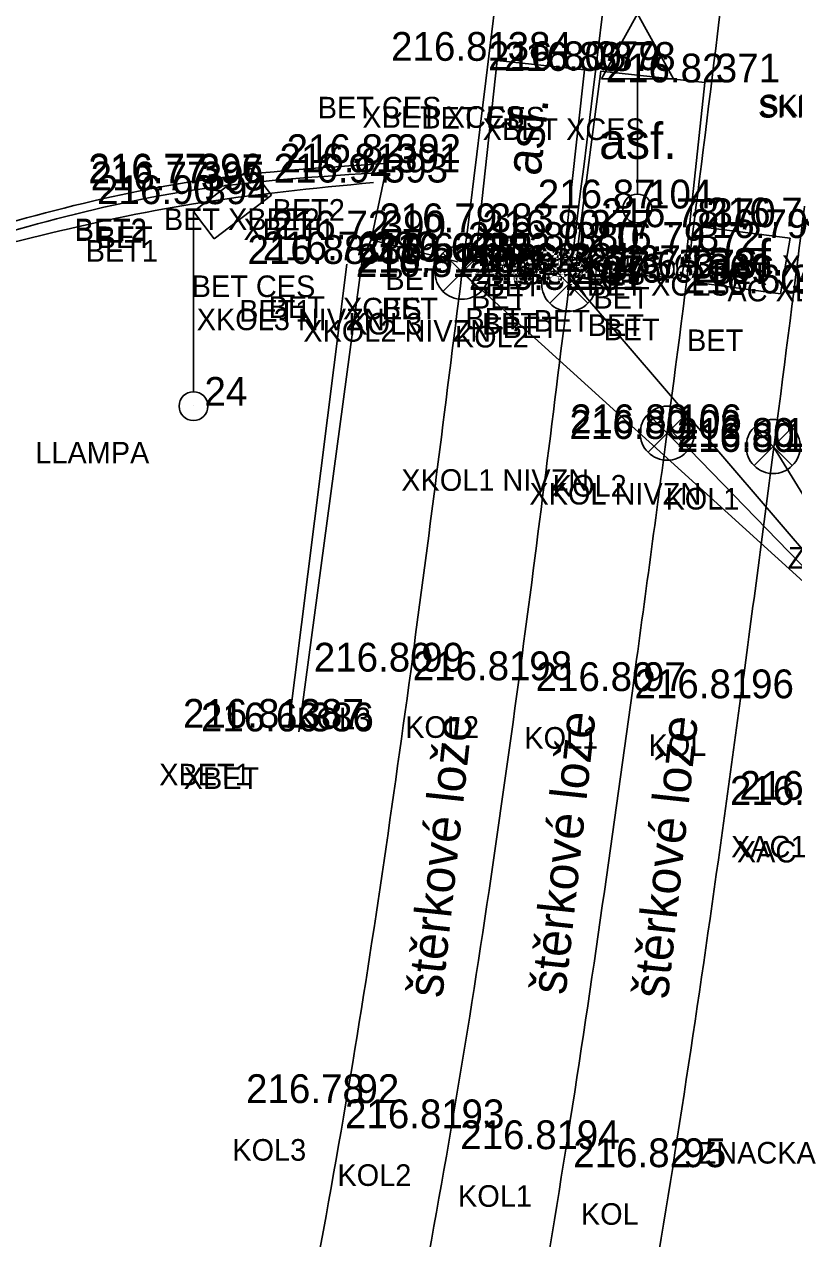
# Model space of a CAD drawing. Extents: x -471047 to -470889, y -1102859 to -1102000.
# Drawn here: x -471009.19 to -470998.51, y -1102775.7 to -1102758.84 of the extents above; entities that cross this region are included whole.
import ezdxf

# ---------------------------------------------------------------- set-up
doc = ezdxf.new("R2010")
doc.units = 0
for name, color, linetype in [('Vrstva 1', 7, 'Continuous'), ('Vrstva 19', 7, 'Continuous'), ('Vrstva 22', 7, 'Continuous'), ('Vrstva 23', 7, 'Continuous'), ('Vrstva 34', 7, 'Continuous'), ('Vrstva 35', 7, 'Continuous'), ('Vrstva 36', 7, 'Continuous'), ('Vrstva 37', 7, 'Continuous'), ('Vrstva 38', 7, 'Continuous'), ('Vrstva 5', 7, 'Continuous'), ('Vrstva 7', 7, 'Continuous'), ('Vrstva 8', 7, 'Continuous')]:
    doc.layers.add(name, color=color, linetype=linetype)

msp = doc.modelspace()

# ---------------------------------------------------------------- linework, layer by layer
at = {"layer": 'Vrstva 1'}
for points in [[(-471040.344, -1102858.385), (-471031.676, -1102846.187), (-471026.357, -1102838.629), (-471023.212, -1102833.975), (-471019.21, -1102827.465), (-471016.861, -1102823.272), (-471013.099, -1102815.912), (-471010.824, -1102810.955), (-471007.329, -1102802.292), (-471005.34, -1102796.515), (-471002.842, -1102787.838), (-471001.3, -1102780.997), (-471000.19, -1102774.713), (-470999.247, -1102768.204), (-470998.794, -1102764.784), (-470997.199, -1102751.812), (-470994.899, -1102732.807), (-470992.551, -1102713.262), (-470990.326, -1102694.887), (-470988.122, -1102676.57), (-470985.812, -1102657.305), (-470983.537, -1102638.407), (-470981.386, -1102620.622), (-470979.843, -1102608.014), (-470976.377, -1102579.253), (-470972.945, -1102550.69), (-470970.475, -1102530.206), (-470967.905, -1102508.801), (-470965.053, -1102485.131), (-470962.734, -1102465.9), (-470960.173, -1102444.812), (-470957.795, -1102425.103), (-470954.965, -1102401.839), (-470953.834, -1102392.574), (-470952.33, -1102379.985), (-470950.744, -1102366.853), (-470948.978, -1102352.106), (-470947.037, -1102335.844), (-470944.949, -1102318.462), (-470944.013, -1102310.745), (-470942.39, -1102297.267), (-470939.519, -1102273.45), (-470937.593, -1102257.43), (-470936.064, -1102244.81), (-470934.114, -1102228.634), (-470931.621, -1102207.856), (-470929.536, -1102190.857), (-470926.572, -1102166.31), (-470924.91, -1102152.663), (-470923.413, -1102140.333), (-470921.923, -1102127.669), (-470921.155, -1102120.084), (-470920.446, -1102109.574), (-470919.912, -1102099.137), (-470919.63, -1102088.981), (-470919.523, -1102081.193), (-470919.563, -1102070.395), (-470919.714, -1102064.236), (-470920.134, -1102054.704), (-470920.462, -1102047.615), (-470920.599, -1102044.52), (-470920.743, -1102041.873), (-470921.125, -1102034.455), (-470921.774, -1102030.337), (-470922.418, -1102027.787), (-470923.734, -1102023.93), (-470924.872, -1102021.434), (-470926.752, -1102018.182), (-470927.953, -1102016.45), (-470929.616, -1102014.424), (-470932.252, -1102011.756), (-470935.111, -1102009.425), (-470938.391, -1102007.371), (-470942.651, -1102005.401)], [(-471041.328, -1102857.18), (-471032.144, -1102844.242), (-471027.583, -1102837.763), (-471024.388, -1102833.028), (-471020.451, -1102826.6), (-471018.089, -1102822.378), (-471014.542, -1102815.445), (-471012.233, -1102810.418), (-471009.247, -1102803.108), (-471006.795, -1102796.098), (-471004.315, -1102787.532), (-471002.782, -1102780.723), (-471001.674, -1102774.458), (-471000.75, -1102768.095), (-471000.28, -1102764.601), (-470998.692, -1102751.741), (-470996.378, -1102732.635), (-470994.028, -1102713.058), (-470991.808, -1102694.749), (-470989.616, -1102676.447), (-470987.284, -1102657.013), (-470985.031, -1102638.272), (-470982.87, -1102620.431), (-470981.334, -1102607.933), (-470977.881, -1102579.263), (-470974.429, -1102550.492), (-470971.964, -1102530.054), (-470969.391, -1102508.607), (-470966.54, -1102484.984), (-470964.231, -1102465.853), (-470961.679, -1102444.752), (-470959.304, -1102425.078), (-470956.455, -1102401.634), (-470955.339, -1102392.489), (-470953.812, -1102379.71), (-470952.249, -1102366.808), (-470950.479, -1102352.023), (-470948.536, -1102335.868), (-470946.426, -1102318.233), (-470945.493, -1102310.531), (-470943.864, -1102297.013), (-470940.984, -1102273.071), (-470939.078, -1102257.195), (-470937.559, -1102244.684), (-470935.592, -1102228.353), (-470933.101, -1102207.653), (-470931.011, -1102190.57), (-470928.046, -1102166.021), (-470926.409, -1102152.578), (-470924.898, -1102140.121), (-470923.427, -1102127.544), (-470922.647, -1102119.826), (-470921.919, -1102109.229), (-470921.42, -1102099.134), (-470921.127, -1102089.016), (-470921.023, -1102081.453), (-470921.061, -1102070.468), (-470921.209, -1102064.314), (-470921.666, -1102053.966), (-470922.156, -1102043.345), (-470922.299, -1102039.934), (-470922.637, -1102034.36), (-470923.091, -1102031.241), (-470923.847, -1102028.247), (-470925.083, -1102024.594), (-470926.222, -1102022.086), (-470928.04, -1102018.943), (-470929.138, -1102017.357), (-470930.929, -1102015.175), (-470933.062, -1102013.049), (-470936.379, -1102010.368), (-470939.169, -1102008.662), (-470942.899, -1102006.906), (-470945.661, -1102005.908)], [(-471043.557, -1102855.955), (-471035.129, -1102844.026), (-471029.872, -1102836.499), (-471026.577, -1102831.578), (-471022.675, -1102825.415), (-471020.123, -1102821.053), (-471016.667, -1102814.59), (-471014.208, -1102809.45), (-471011.177, -1102802.451), (-471008.55, -1102795.333), (-471006.082, -1102787.209), (-471004.464, -1102780.376), (-471003.265, -1102774.167), (-471002.327, -1102767.948), (-471001.636, -1102762.527), (-471000.297, -1102751.605), (-470997.959, -1102732.524), (-470995.602, -1102712.802), (-470993.412, -1102694.623), (-470991.21, -1102676.17), (-470988.891, -1102656.857), (-470986.625, -1102638.083), (-470984.455, -1102620.195), (-470982.936, -1102607.733), (-470979.497, -1102579.223), (-470976.023, -1102550.279), (-470973.554, -1102529.822), (-470970.991, -1102508.497), (-470968.146, -1102484.787), (-470965.835, -1102465.72), (-470963.284, -1102444.529), (-470960.91, -1102424.942), (-470958.043, -1102401.343), (-470956.946, -1102392.356), (-470955.396, -1102379.408), (-470953.851, -1102366.636), (-470952.049, -1102351.733), (-470950.124, -1102335.611), (-470948.034, -1102318.083), (-470947.094, -1102310.328), (-470945.421, -1102296.51), (-470942.58, -1102272.848), (-470940.675, -1102256.948), (-470939.176, -1102244.526), (-470937.187, -1102228.174), (-470934.708, -1102207.467), (-470932.621, -1102190.433), (-470929.634, -1102165.778), (-470928.004, -1102152.415), (-470926.45, -1102139.595), (-470925.003, -1102127.418), (-470924.249, -1102119.695), (-470923.515, -1102109.093), (-470923.018, -1102099.069), (-470922.711, -1102088.911), (-470922.643, -1102081.356), (-470922.797, -1102070.414), (-470923.018, -1102064.454), (-470923.52, -1102053.203), (-470923.823, -1102047.529), (-470924.123, -1102041.506), (-470924.462, -1102037.486), (-470924.934, -1102031.904), (-470925.664, -1102028.672), (-470926.771, -1102025.506), (-470927.959, -1102022.914), (-470929.674, -1102020.028), (-470930.76, -1102018.498), (-470932.447, -1102016.478), (-470935.215, -1102013.816), (-470937.644, -1102011.98), (-470940.381, -1102010.371), (-470943.968, -1102008.669), (-470947.145, -1102007.524), (-470950.874, -1102006.74)], [(-471044.756, -1102855.056), (-471036.376, -1102843.177), (-471031.167, -1102835.741), (-471027.859, -1102830.8), (-471023.934, -1102824.593), (-471021.43, -1102820.312), (-471018.011, -1102813.91), (-471015.536, -1102808.75), (-471012.578, -1102801.897), (-471009.95, -1102794.77), (-471007.561, -1102786.914), (-471005.936, -1102780.074), (-471004.727, -1102773.818), (-471003.828, -1102767.827), (-471003.121, -1102762.345), (-471001.787, -1102751.467), (-470999.446, -1102732.348), (-470997.073, -1102712.539), (-470994.902, -1102694.521), (-470992.696, -1102676.023), (-470990.376, -1102656.68), (-470988.131, -1102638.071), (-470985.947, -1102620.018), (-470984.417, -1102607.512), (-470980.993, -1102579.08), (-470977.514, -1102550.137), (-470975.048, -1102529.649), (-470972.488, -1102508.37), (-470969.618, -1102484.508), (-470967.34, -1102465.669), (-470964.767, -1102444.39), (-470962.402, -1102424.781), (-470959.534, -1102401.193), (-470958.432, -1102392.151), (-470956.883, -1102379.208), (-470955.335, -1102366.424), (-470953.535, -1102351.506), (-470951.606, -1102335.399), (-470949.519, -1102317.94), (-470948.575, -1102310.159), (-470946.889, -1102296.144), (-470944.056, -1102272.618), (-470942.139, -1102256.659), (-470940.657, -1102244.341), (-470938.638, -1102227.749), (-470936.19, -1102207.298), (-470934.102, -1102190.255), (-470931.124, -1102165.639), (-470929.492, -1102152.254), (-470927.915, -1102139.252), (-470926.46, -1102127.103), (-470925.74, -1102119.604), (-470925.012, -1102108.913), (-470924.523, -1102099.054), (-470924.217, -1102088.866), (-470924.148, -1102081.334), (-470924.301, -1102070.391), (-470924.518, -1102064.43), (-470924.97, -1102054.435), (-470925.588, -1102041.569), (-470925.963, -1102035.313), (-470926.405, -1102032.225), (-470927.078, -1102029.198), (-470928.123, -1102026.148), (-470929.318, -1102023.558), (-470930.84, -1102020.97), (-470931.868, -1102019.515), (-470933.443, -1102017.605), (-470936.26, -1102014.885), (-470938.429, -1102013.255), (-470941.213, -1102011.639), (-470944.847, -1102009.927), (-470947.723, -1102008.912), (-470951.444, -1102008.161), (-470954.511, -1102007.931), (-470957.895, -1102008.041)]]:
    msp.add_spline(points, degree=3, dxfattribs=at)
at = {"layer": 'Vrstva 19'}
for p, q in [((-471000.68, -1102758.7), (-471001.18, -1102759.6)), ((-471000.68, -1102758.7), (-471000.18, -1102759.6)), ((-471000.18, -1102759.6), (-471001.18, -1102759.6)), ((-471000.68, -1102759.6), (-471000.68, -1102761.2))]:
    msp.add_line(p, q, dxfattribs=at)
msp.add_circle((-471000.68, -1102761.4), 0.2, dxfattribs=at)
at = {"layer": 'Vrstva 22'}
for q in [(-471003.11, -1102762.29), (-471001.617, -1102762.368), (-471000.259, -1102764.436), (-470998.79, -1102764.71)]:
    msp.add_line((-470996.706, -1102768.099), q, dxfattribs=at)
at = {"layer": 'Vrstva 23'}
for p, q in [((-471006.049, -1102760.839), (-471006.844, -1102761.444)), ((-471005.759, -1102761.216), (-471006.049, -1102760.839)), ((-471006.556, -1102761.822), (-471005.759, -1102761.216)), ((-471006.844, -1102761.444), (-471006.844, -1102763.944)), ((-471006.844, -1102761.444), (-471006.556, -1102761.822))]:
    msp.add_line(p, q, dxfattribs=at)
msp.add_circle((-471006.844, -1102764.144), 0.2, dxfattribs=at)
at = {"layer": 'Vrstva 34'}
for p, q in [((-471002.63, -1102759.35), (-471002.63, -1102759.35)), ((-471001.41, -1102759.48), (-471001.41, -1102759.48)), ((-471001.19, -1102759.49), (-471001.19, -1102759.49)), ((-470999.74, -1102759.65), (-470999.74, -1102759.65)), ((-471004.17, -1102760.77), (-471004.17, -1102760.77)), ((-471004.18, -1102760.9), (-471004.18, -1102760.9)), ((-471006.92, -1102761.04), (-471006.92, -1102761.04)), ((-471006.92, -1102761.05), (-471006.92, -1102761.05)), ((-471006.89, -1102761.15), (-471006.89, -1102761.15)), ((-471004.35, -1102761.04), (-471004.35, -1102761.04)), ((-471006.84, -1102761.34), (-471006.84, -1102761.34)), ((-471000.68, -1102761.4), (-471000.68, -1102761.4)), ((-470999.8, -1102761.66), (-470999.8, -1102761.66)), ((-471004.38, -1102761.83), (-471004.38, -1102761.83)), ((-471002.88, -1102761.73), (-471002.88, -1102761.73)), ((-471001.49, -1102761.82), (-471001.49, -1102761.82)), ((-470998.56, -1102761.81), (-470998.56, -1102761.81)), ((-471001.69, -1102761.99), (-471001.69, -1102761.99)), ((-470999.99, -1102761.99), (-470999.99, -1102761.99)), ((-471004.71, -1102762.17), (-471004.71, -1102762.17)), ((-471004.5, -1102762.12), (-471004.5, -1102762.12)), ((-471003.18, -1102762.14), (-471003.18, -1102762.14)), ((-471002.93, -1102762.14), (-471002.93, -1102762.14)), ((-471003.12, -1102762.35), (-471003.12, -1102762.35)), ((-471003.11, -1102762.29), (-471003.11, -1102762.29)), ((-471001.77, -1102762.28), (-471001.77, -1102762.28)), ((-471001.54, -1102762.35), (-471001.54, -1102762.35)), ((-471000.82, -1102762.31), (-471000.82, -1102762.31)), ((-471001.63, -1102762.45), (-471001.63, -1102762.45)), ((-471001.25, -1102762.4), (-471001.25, -1102762.4)), ((-471000.07, -1102762.37), (-471000.07, -1102762.37)), ((-470999.85, -1102762.43), (-470999.85, -1102762.43)), ((-471001.64, -1102762.53), (-471001.64, -1102762.53)), ((-470998.69, -1102762.58), (-470998.69, -1102762.58)), ((-471006.84, -1102764.14), (-471006.84, -1102764.14)), ((-471000.27, -1102764.52), (-471000.27, -1102764.52)), ((-471000.28, -1102764.6), (-471000.28, -1102764.6)), ((-470998.79, -1102764.71), (-470998.79, -1102764.71)), ((-470998.79, -1102764.78), (-470998.79, -1102764.78)), ((-471003.83, -1102767.83), (-471003.83, -1102767.83)), ((-471002.33, -1102767.95), (-471002.33, -1102767.95)), ((-471000.75, -1102768.1), (-471000.75, -1102768.1)), ((-470999.25, -1102768.2), (-470999.25, -1102768.2)), ((-471005.52, -1102768.61), (-471005.52, -1102768.61)), ((-471005.38, -1102768.66), (-471005.38, -1102768.66)), ((-471004.73, -1102773.82), (-471004.73, -1102773.82)), ((-471003.27, -1102774.17), (-471003.27, -1102774.17)), ((-471001.67, -1102774.46), (-471001.67, -1102774.46)), ((-471000.19, -1102774.71), (-471000.19, -1102774.71))]:
    msp.add_line(p, q, dxfattribs=at)
at = {"layer": 'Vrstva 37'}
for p, q in [((-471003.38, -1102762.021), (-471003.115, -1102762.286)), ((-471002.85, -1102762.021), (-471003.115, -1102762.286)), ((-471002.85, -1102762.021), (-471002.85, -1102762.021)), ((-471001.897, -1102762.186), (-471001.632, -1102762.451)), ((-471001.367, -1102762.186), (-471001.632, -1102762.451)), ((-471001.367, -1102762.186), (-471001.367, -1102762.186)), ((-471003.115, -1102762.286), (-471003.38, -1102762.551)), ((-471003.115, -1102762.286), (-471002.85, -1102762.551)), ((-471001.632, -1102762.451), (-471001.897, -1102762.716)), ((-471001.632, -1102762.451), (-471001.367, -1102762.716)), ((-471000.531, -1102764.255), (-471000.266, -1102764.52)), ((-471000.001, -1102764.255), (-471000.266, -1102764.52)), ((-471000.001, -1102764.255), (-471000.001, -1102764.255)), ((-471000.266, -1102764.52), (-471000.531, -1102764.785)), ((-471000.266, -1102764.52), (-471000.001, -1102764.785)), ((-470999.059, -1102764.44), (-470998.794, -1102764.705)), ((-470998.529, -1102764.44), (-470998.794, -1102764.705)), ((-470998.529, -1102764.44), (-470998.529, -1102764.44)), ((-470998.794, -1102764.705), (-470999.059, -1102764.97)), ((-470998.794, -1102764.705), (-470998.529, -1102764.97))]:
    msp.add_line(p, q, dxfattribs=at)
for centre, start, end in [((-471003.115, -1102762.286), 135, 224.9643), ((-471003.115, -1102762.286), 45, 134.9643), ((-471003.115, -1102762.286), 315, 44.9643), ((-471001.632, -1102762.451), 135, 224.9643), ((-471001.632, -1102762.451), 45, 134.9643), ((-471001.632, -1102762.451), 315, 44.9643), ((-471003.115, -1102762.286), 225, 314.9643), ((-471001.632, -1102762.451), 225, 314.9643), ((-471000.266, -1102764.52), 45, 134.9643), ((-471000.266, -1102764.52), 135, 224.9643), ((-471000.266, -1102764.52), 315, 44.9643), ((-470998.794, -1102764.705), 45, 134.9643), ((-470998.794, -1102764.705), 135, 224.9643), ((-470998.794, -1102764.705), 315, 44.9643), ((-471000.266, -1102764.52), 225, 314.9643), ((-470998.794, -1102764.705), 225, 314.9643)]:
    msp.add_arc(centre, 0.375, start, end, dxfattribs=at)
at = {"layer": 'Vrstva 5'}
for p, q in [((-471004.177, -1102760.897), (-471004.17, -1102760.774)), ((-471006.92, -1102761.036), (-471006.924, -1102761.047))]:
    msp.add_line(p, q, dxfattribs=at)
msp.add_spline([(-471011.116, -1102762.107), (-471006.92, -1102761.036), (-471004.17, -1102760.774)], degree=3, dxfattribs=at)
at = {"layer": 'Vrstva 7'}
msp.add_line((-471005.523, -1102768.609), (-471004.714, -1102762.172), dxfattribs=at)
msp.add_spline([(-471011.067, -1102762.33), (-471006.844, -1102761.336), (-471004.346, -1102761.039)], degree=3, dxfattribs=at)
at = {"layer": 'Vrstva 8'}
for p, q in [((-471002.884, -1102761.731), (-471002.628, -1102759.346)), ((-471001.413, -1102759.476), (-471002.628, -1102759.346)), ((-471001.413, -1102759.476), (-471001.692, -1102761.986)), ((-471001.492, -1102761.817), (-471001.187, -1102759.492)), ((-470999.743, -1102759.65), (-471001.187, -1102759.492)), ((-470999.743, -1102759.65), (-470999.993, -1102761.987)), ((-471004.379, -1102761.834), (-471004.177, -1102760.897)), ((-470999.853, -1102762.426), (-470999.803, -1102761.655)), ((-470998.557, -1102761.812), (-470999.803, -1102761.655)), ((-471004.5, -1102762.116), (-471004.379, -1102761.834)), ((-471003.177, -1102762.143), (-471004.379, -1102761.834)), ((-471002.934, -1102762.141), (-471002.884, -1102761.731)), ((-471001.54, -1102762.353), (-471001.492, -1102761.817)), ((-470998.557, -1102761.812), (-470998.694, -1102762.584)), ((-471001.692, -1102761.986), (-471001.768, -1102762.282)), ((-470999.993, -1102761.987), (-471000.071, -1102762.373)), ((-471005.38, -1102768.664), (-471004.5, -1102762.116)), ((-471001.768, -1102762.282), (-471002.934, -1102762.141)), ((-471001.251, -1102762.402), (-471001.54, -1102762.353)), ((-471000.824, -1102762.311), (-471001.251, -1102762.402)), ((-471000.071, -1102762.373), (-471000.824, -1102762.311)), ((-470998.694, -1102762.584), (-470999.853, -1102762.426))]:
    msp.add_line(p, q, dxfattribs=at)
msp.add_spline([(-471011.104, -1102762.232), (-471006.89, -1102761.152), (-471004.177, -1102760.897)], degree=3, dxfattribs=at)

# ---------------------------------------------------------------- texts
at = {"layer": 'Vrstva 22'}
for s, p in [('asf.', (-471002.026, -1102760.959)), ('štěrkové lože', (-471001.678, -1102772.327)), ('štěrkové lože', (-471003.389, -1102772.37)), ('štěrkové lože', (-471000.257, -1102772.385))]:
    msp.add_text(s, height=0.5, rotation=83.8735, dxfattribs=at).set_placement(p)
for p in [(-471001.211, -1102760.712), (-470999.718, -1102762.332)]:
    msp.add_text('asf.', height=0.5, dxfattribs=at).set_placement(p)
at = {"layer": 'Vrstva 35'}
for s, p in [('SKRUH', (-470998.985, -1102760.12)), ('BET CES', (-471005.119, -1102760.15)), ('XBET XCES', (-471004.499, -1102760.28)), ('BET CES', (-471003.679, -1102760.29)), ('SKRUH', (-470999.005, -1102760.14)), ('XBET XCES', (-471002.829, -1102760.45)), ('BET2', (-471005.745, -1102761.57)), ('BET XBET2', (-471007.255, -1102761.7)), ('BET2', (-471008.495, -1102761.84)), ('BET2', (-471008.495, -1102761.85)), ('BET', (-471008.19, -1102761.95)), ('XBET1', (-471006.15, -1102761.84)), ('BET1', (-471008.34, -1102762.14)), ('ZNACKA', (-471002.88, -1102762.2)), ('BET CES', (-471002.289, -1102762.46)), ('BET', (-470999.64, -1102762.45)), ('AC XAC2', (-470999.345, -1102762.35)), ('BET CES', (-471006.869, -1102762.63)), ('BET', (-471004.18, -1102762.53)), ('BET', (-471002.79, -1102762.62)), ('XBET XCES', (-471001.649, -1102762.61)), ('BET', (-471002.99, -1102762.79)), ('BET', (-471001.29, -1102762.79)), ('AC XBET', (-470999.43, -1102762.69)), ('BET1', (-471006.21, -1102762.97)), ('BET', (-471005.8, -1102762.92)), ('XCES', (-471004.769, -1102762.94)), ('BET', (-471004.23, -1102762.94)), ('XKOL3 NIVZN', (-471006.799, -1102763.09)), ('KOL3', (-471004.695, -1102763.15)), ('BET', (-471003.07, -1102763.08)), ('BET', (-471002.84, -1102763.15)), ('BET', (-471002.12, -1102763.11)), ('XKOL2 NIVZN', (-471005.319, -1102763.25)), ('KOL2', (-471003.215, -1102763.33)), ('BET', (-471002.55, -1102763.2)), ('BET', (-471001.37, -1102763.17)), ('BET', (-471001.15, -1102763.23)), ('BET', (-470999.99, -1102763.38)), ('LLAMPA', (-471009.04, -1102764.94)), ('XKOL1 NIVZN', (-471003.959, -1102765.32)), ('XKOL NIVZN', (-471002.179, -1102765.51)), ('KOL2', (-471001.855, -1102765.4)), ('KOL1', (-471000.29, -1102765.58)), ('ZNACKA', (-470998.59, -1102766.4)), ('KOL3', (-471005.405, -1102768.63)), ('KOL2', (-471003.905, -1102768.75)), ('KOL1', (-471002.25, -1102768.9)), ('KOL', (-471000.525, -1102769)), ('XBET1', (-471007.32, -1102769.41)), ('XBET', (-471006.98, -1102769.46)), ('XAC1', (-470999.38, -1102770.41)), ('XAC', (-470999.299, -1102770.48)), ('KOL3', (-471006.305, -1102774.62)), ('ZNACKA', (-470999.83, -1102774.66)), ('KOL2', (-471004.845, -1102774.97)), ('KOL1', (-471003.17, -1102775.26)), ('KOL', (-471001.465, -1102775.51))]:
    msp.add_text(s, height=0.3, dxfattribs=at).set_placement(p)
at = {"layer": 'Vrstva 36'}
for s, p in [(' 384', (-471002.63, -1102759.35)), (' 379', (-471001.41, -1102759.48)), (' 378', (-471001.19, -1102759.49)), (' 371', (-470999.74, -1102759.65)), (' 391', (-471004.18, -1102760.9)), (' 392', (-471004.17, -1102760.77)), (' 396', (-471006.92, -1102761.04)), (' 397', (-471006.92, -1102761.05)), (' 393', (-471004.35, -1102761.04)), (' 395', (-471006.89, -1102761.15)), (' 394', (-471006.84, -1102761.34)), (' 104', (-471000.68, -1102761.4)), (' 383', (-471002.88, -1102761.73)), (' 370', (-470999.8, -1102761.66)), (' 390', (-471004.38, -1102761.83)), (' 377', (-471001.49, -1102761.82)), (' 380', (-471001.69, -1102761.99)), (' 372', (-470999.99, -1102761.99)), (' 388', (-471004.71, -1102762.17)), (' 389', (-471004.5, -1102762.12)), (' 385', (-471003.18, -1102762.14)), (' 382', (-471002.93, -1102762.14)), (' 100', (-471003.12, -1102762.35)), (' 108', (-471003.11, -1102762.29)), (' 381', (-471001.77, -1102762.28)), (' 376', (-471001.54, -1102762.35)), (' 375', (-471001.25, -1102762.4)), (' 374', (-471000.82, -1102762.31)), (' 373', (-471000.07, -1102762.37)), (' 101', (-471001.64, -1102762.53)), (' 107', (-471001.63, -1102762.45)), (' 369', (-470999.85, -1102762.43)), (' 368', (-470998.69, -1102762.58)), (' 24', (-471006.84, -1102764.14)), (' 102', (-471000.28, -1102764.6)), (' 106', (-471000.27, -1102764.52)), (' 105', (-470998.79, -1102764.71)), (' 103', (-470998.79, -1102764.78)), (' 99', (-471003.83, -1102767.83)), (' 98', (-471002.33, -1102767.95)), (' 97', (-471000.75, -1102768.1)), (' 96', (-470999.25, -1102768.2)), (' 387', (-471005.52, -1102768.61)), (' 386', (-471005.38, -1102768.66)), (' 92', (-471004.73, -1102773.82)), (' 93', (-471003.27, -1102774.17)), (' 94', (-471001.67, -1102774.46)), (' 95', (-471000.19, -1102774.71))]:
    msp.add_text(s, height=0.4, dxfattribs=at).set_placement(p)
at = {"layer": 'Vrstva 38'}
for s, p in [('216.81 ', (-471004.1, -1102759.35)), ('216.80 ', (-471002.753, -1102759.48)), ('216.80 ', (-471002.533, -1102759.49)), ('216.82 ', (-471001.121, -1102759.65)), ('216.81 ', (-471005.65, -1102760.9)), ('216.82 ', (-471005.551, -1102760.77)), ('216.77 ', (-471008.303, -1102761.04)), ('216.77 ', (-471008.303, -1102761.05)), ('216.94 ', (-471005.732, -1102761.04)), ('216.77 ', (-471008.273, -1102761.15)), ('216.90 ', (-471008.183, -1102761.34)), ('216.87 ', (-471002.063, -1102761.4)), ('216.79 ', (-471004.264, -1102761.73)), ('216.78 ', (-471001.184, -1102761.66)), ('216.73 ', (-470999.723, -1102761.65)), ('216.72 ', (-471005.761, -1102761.83)), ('216.80 ', (-471002.833, -1102761.82)), ('216.79 ', (-470999.944, -1102761.81)), ('216.80 ', (-471003.033, -1102761.99)), ('216.79 ', (-471001.374, -1102761.99)), ('216.88 ', (-471006.094, -1102762.17)), ('216.72 ', (-471005.881, -1102762.12)), ('216.63 ', (-471004.563, -1102762.14)), ('216.67 ', (-471004.313, -1102762.14)), ('216.81 ', (-471004.59, -1102762.35)), ('216.81 ', (-471004.58, -1102762.29)), ('216.62 ', (-471003.151, -1102762.28)), ('216.64 ', (-471002.922, -1102762.35)), ('216.61 ', (-471002.72, -1102762.4)), ('216.63 ', (-471002.203, -1102762.31)), ('216.65 ', (-471001.454, -1102762.37)), ('216.82 ', (-471003.021, -1102762.53)), ('216.82 ', (-471003.011, -1102762.45)), ('216.62 ', (-471001.231, -1102762.43)), ('216.60 ', (-471000.033, -1102762.58)), ('216.80 ', (-471001.623, -1102764.6)), ('216.80 ', (-471001.613, -1102764.52)), ('216.80 ', (-471000.133, -1102764.71)), ('216.80 ', (-471000.133, -1102764.78)), ('216.80 ', (-471005.173, -1102767.83)), ('216.81 ', (-471003.8, -1102767.95)), ('216.80 ', (-471002.093, -1102768.1)), ('216.81 ', (-471000.72, -1102768.2)), ('216.81 ', (-471006.99, -1102768.61)), ('216.66 ', (-471006.74, -1102768.66)), ('216.83 ', (-470999.263, -1102769.61)), ('216.59 ', (-470999.394, -1102769.68)), ('216.78 ', (-471006.114, -1102773.82)), ('216.81 ', (-471004.74, -1102774.17)), ('216.81 ', (-471003.14, -1102774.46)), ('216.82 ', (-471001.571, -1102774.71))]:
    msp.add_text(s, height=0.4, dxfattribs=at).set_placement(p)

doc.saveas('drawing.dxf')
